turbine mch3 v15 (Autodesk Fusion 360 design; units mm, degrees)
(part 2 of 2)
sketch "Sketch44" plane through (0, -88, 0) normal (0, 1, 0) x axis (-1, 0, 0)
  line L1 (29.584, -10.378) -> (42.9468, -10.378)
  line L2 (29.584, 9.622) -> (29.584, -10.378)
  line L3 (48.5431, 9.622) -> (29.584, 9.622)
  line L4 (48.5431, -0.6848) -> (48.5431, 9.622)
  line L5 (59.9482, 19.0693) -> (48.5431, -0.6848)
  line L6 (63.7853, 19.9155) -> (59.9482, 19.0693)
  line L7 (46.4835, 42.382) -> (49.2565, 45.1551)
  line L8 (-46.4886, 42.382) -> (46.4835, 42.382)
  line L9 (-49.14, 45.2819) -> (-46.4886, 42.382)
  line L10 (-59.9456, 19.0649) -> (-63.7337, 20.0799)
  line L11 (-13.4596, -61.4513) -> (-59.9456, 19.0649)
  line L12 (-14.6453, -65.1974) -> (-13.4596, -61.4513)
  line L13 (13.4622, -61.4469) -> (14.4772, -65.235)
  line L14 (42.9468, -10.378) -> (13.4622, -61.4469)
  line L15 (16.2634, -23.1918) -> (16.634, -23.5625)
  line L16 (23.1436, -16.2151) -> (16.2634, -23.1918)
  line L17 (23.6506, -14.1336) -> (23.1436, -16.2151)
  line L18 (22.2443, -12.7273) -> (23.6506, -14.1336)
  line L19 (26.0227, -8.9488) -> (22.2443, -12.7273)
  line L20 (-16.2634, 23.1918) -> (-16.634, 23.5625)
  line L21 (-23.1436, 16.2151) -> (-16.2634, 23.1918)
  line L22 (-23.6506, 14.1336) -> (-23.1436, 16.2151)
  line L23 (-22.2443, 12.7273) -> (-23.6506, 14.1336)
  line L24 (-26.0227, 8.9488) -> (-22.2443, 12.7273)
  line L25 (-23.1918, -16.2634) -> (-23.5625, -16.634)
  line L26 (-16.2151, -23.1436) -> (-23.1918, -16.2634)
  line L27 (-14.1336, -23.6506) -> (-16.2151, -23.1436)
  line L28 (-12.7273, -22.2443) -> (-14.1336, -23.6506)
  line L29 (-8.9488, -26.0227) -> (-12.7273, -22.2443)
  line L30 (-36.2227, 9.0209) -> (-43.1621, 7.1615)
  line L31 (-38.7627, 4.6215) -> (-36.2227, 9.0209)
  line L32 (-43.1621, 7.1615) -> (-38.7627, 4.6215)
  line L33 (-52.8906, 15.7112) -> (-54.1606, 13.5115)
  line L34 (-51.9609, 12.2415) -> (-52.8906, 15.7112)
  line L35 (-54.1606, 13.5115) -> (-51.9609, 12.2415)
  line L36 (-42.0956, 34.4087) -> (-38.6259, 35.3384)
  line L37 (-37.6506, 42.1077) -> (-42.0956, 34.4087)
  line L38 (-33.2512, 39.5677) -> (-37.6506, 42.1077)
  line L39 (-36.7209, 38.638) -> (-33.2512, 39.5677)
  line L40 (-38.6259, 35.3384) -> (-36.7209, 38.638)
  line L41 (-24.7927, 28.8183) -> (-22.2527, 33.2177)
  line L42 (-26.6521, 35.7577) -> (-24.7927, 28.8183)
  line L43 (-22.2527, 33.2177) -> (-26.6521, 35.7577)
  line L44 (-18.5, 42.141) -> (-20.5, 42.141)
  line L45 (-18.5, 25) -> (-18.5, 42.141)
  line L46 (-20.5, 25) -> (-18.5, 25)
  line L47 (-20.5, 42.141) -> (-20.5, 25)
  line L48 (16, 26.3899) -> (16, 42.141)
  line L49 (23.1918, 16.2634) -> (23.5625, 16.634)
  line L50 (16.2151, 23.1436) -> (23.1918, 16.2634)
  line L51 (14.1336, 23.6506) -> (16.2151, 23.1436)
  line L52 (12.7273, 22.2443) -> (14.1336, 23.6506)
  line L53 (8.9488, 26.0227) -> (12.7273, 22.2443)
  line L54 (13.5, 42.141) -> (13.5, 26.8143)
  line L55 (16, 42.141) -> (13.5, 42.141)
  line L56 (-43.2694, 24.4155) -> (-22.8556, 24.4155)
  line L57 (-43.2694, 42.382) -> (-43.2694, 24.4155)
  line L58 (-22.8556, 42.382) -> (-43.2694, 42.382)
  line L59 (-22.8556, 24.4155) -> (-22.8556, 42.382)
  line L60 (-55.5462, 13.5115) -> (-38.7012, 1.0039)
  line L61 (-43.2694, 33.3988) -> (-55.5462, 13.5115)
  line L62 (-28.423, 24.4155) -> (-37.7467, 2.2894)
  arc A1 centre (0, 0) radius 66.8221 clockwise from (49.2565, 45.1551) to (63.7853, 19.9155)
  arc A2 centre (0, 0) radius 66.8221 clockwise from (-63.7337, 20.0799) to (-49.14, 45.2819)
  arc A3 centre (0, 0) radius 66.8221 clockwise from (14.4772, -65.235) to (-14.6453, -65.1974)
  arc A4 centre (16.2499, -12.9929) radius 10.5766 clockwise from (26.0227, -8.9488) to (16.634, -23.5625)
  arc A5 centre (-16.2499, 12.9929) radius 10.5766 clockwise from (-26.0227, 8.9488) to (-16.634, 23.5625)
  arc A6 centre (-12.9929, -16.2499) radius 10.5766 clockwise from (-8.9488, -26.0227) to (-23.5625, -16.634)
  arc A7 centre (12.9929, 16.2499) radius 10.5766 clockwise from (16, 26.3899) to (23.5625, 16.634)
  arc A8 centre (12.9929, 16.2499) radius 10.5766 clockwise from (8.9488, 26.0227) to (13.5, 26.8143)
  arc A9 centre (-38.224, 1.6467) radius 0.8006 clockwise from (-37.7467, 2.2894) to (-38.7012, 1.0039)
extrude "Extrude44" cut sketch "Sketch44" profile of L41 L43 L59 along normal blind 5
extrude "Extrude43" cut sketch "Sketch44" profile of L30 L31 L32 L33 L34 L35 L36 L37 L38 L39 L40 L41 L42 L43 L59 along normal blind 5
sketch "Sketch45" plane through (0, -88, 0) normal (0, 1, 0) x axis (-1, 0, 0)
  line L1 (29.584, -10.378) -> (42.9468, -10.378)
  line L2 (29.584, 9.622) -> (29.584, -10.378)
  line L3 (48.5431, 9.622) -> (29.584, 9.622)
  line L4 (48.5431, -0.6848) -> (48.5431, 9.622)
  line L5 (59.9482, 19.0693) -> (48.5431, -0.6848)
  line L6 (63.7853, 19.9155) -> (59.9482, 19.0693)
  line L7 (46.4835, 42.382) -> (49.2565, 45.1551)
  line L8 (-46.4886, 42.382) -> (46.4835, 42.382)
  line L9 (-49.14, 45.2819) -> (-46.4886, 42.382)
  line L10 (-59.9456, 19.0649) -> (-63.7337, 20.0799)
  line L11 (-13.4596, -61.4513) -> (-59.9456, 19.0649)
  line L12 (-14.6453, -65.1974) -> (-13.4596, -61.4513)
  line L13 (13.4622, -61.4469) -> (14.4772, -65.235)
  line L14 (42.9468, -10.378) -> (13.4622, -61.4469)
  line L15 (16.2634, -23.1918) -> (16.634, -23.5625)
  line L16 (23.1436, -16.2151) -> (16.2634, -23.1918)
  line L17 (23.6506, -14.1336) -> (23.1436, -16.2151)
  line L18 (22.2443, -12.7273) -> (23.6506, -14.1336)
  line L19 (26.0227, -8.9488) -> (22.2443, -12.7273)
  line L20 (-16.2634, 23.1918) -> (-16.634, 23.5625)
  line L21 (-23.1436, 16.2151) -> (-16.2634, 23.1918)
  line L22 (-23.6506, 14.1336) -> (-23.1436, 16.2151)
  line L23 (-22.2443, 12.7273) -> (-23.6506, 14.1336)
  line L24 (-26.0227, 8.9488) -> (-22.2443, 12.7273)
  line L25 (-23.1918, -16.2634) -> (-23.5625, -16.634)
  line L26 (-16.2151, -23.1436) -> (-23.1918, -16.2634)
  line L27 (-14.1336, -23.6506) -> (-16.2151, -23.1436)
  line L28 (-12.7273, -22.2443) -> (-14.1336, -23.6506)
  line L29 (-8.9488, -26.0227) -> (-12.7273, -22.2443)
  line L30 (-18.5, 42.141) -> (-20.5, 42.141)
  line L31 (-18.5, 25) -> (-18.5, 42.141)
  line L32 (-20.5, 25) -> (-18.5, 25)
  line L33 (-20.5, 42.141) -> (-20.5, 25)
  line L34 (16, 26.3899) -> (16, 42.141)
  line L35 (23.1918, 16.2634) -> (23.5625, 16.634)
  line L36 (16.2151, 23.1436) -> (23.1918, 16.2634)
  line L37 (14.1336, 23.6506) -> (16.2151, 23.1436)
  line L38 (12.7273, 22.2443) -> (14.1336, 23.6506)
  line L39 (8.9488, 26.0227) -> (12.7273, 22.2443)
  line L40 (13.5, 42.141) -> (13.5, 26.8143)
  line L41 (16, 42.141) -> (13.5, 42.141)
  line L42 (-55.7513, 18.9527) -> (-56.6274, 15.683)
  line L43 (-54.8883, 19.0667) -> (-55.8181, 15.597)
  line L44 (-57.6394, 22.1819) -> (-55.7513, 18.9527)
  line L45 (-56.4984, 26.4403) -> (-57.6394, 22.1819)
  line L46 (-49.2689, 30.6675) -> (-56.4984, 26.4403)
  line L47 (-41.82, 28.6716) -> (-49.2689, 30.6675)
  line L48 (-28.0102, 5.0536) -> (-41.82, 28.6716)
  line L49 (-30.2147, -3.1739) -> (-28.0102, 5.0536)
  line L50 (-41.0409, -9.5042) -> (-30.2147, -3.1739)
  line L51 (-43.9219, -8.689) -> (-41.0409, -9.5042)
  line L52 (-45.7338, -3.1852) -> (-46.183, -4.7727)
  line L53 (-56.6274, 15.683) -> (-45.7338, -3.1852)
  line L54 (-55.8181, 15.597) -> (-45.0231, -3.1005)
  line L55 (-30.8495, -2.2498) -> (-41.8481, -8.5998)
  line L56 (-47.9432, 0.6415) -> (-48.9675, 0.0501)
  line L57 (-58.5686, 18.7141) -> (-57.6394, 22.1819)
  line L58 (-56.6274, 15.3519) -> (-58.5686, 18.7141)
  line L59 (-56.6274, 15.683) -> (-56.6274, 15.3519)
  line L60 (-45, 32) -> (-43.1941, 29.0398)
  line L61 (-47.8204, 30.2794) -> (-45, 32)
  line L62 (-27.1598, -0.4207) -> (-28.7698, 2.2185)
  line L63 (-29.9298, -2.1105) -> (-27.1598, -0.4207)
  arc A1 centre (0, 0) radius 66.8221 clockwise from (49.2565, 45.1551) to (63.7853, 19.9155)
  arc A2 centre (0, 0) radius 66.8221 clockwise from (-63.7337, 20.0799) to (-49.14, 45.2819)
  arc A3 centre (0, 0) radius 66.8221 clockwise from (14.4772, -65.235) to (-14.6453, -65.1974)
  arc A4 centre (16.2499, -12.9929) radius 10.5766 clockwise from (26.0227, -8.9488) to (16.634, -23.5625)
  arc A5 centre (-16.2499, 12.9929) radius 10.5766 clockwise from (-26.0227, 8.9488) to (-16.634, 23.5625)
  arc A6 centre (-12.9929, -16.2499) radius 10.5766 clockwise from (-8.9488, -26.0227) to (-23.5625, -16.634)
  arc A7 centre (12.9929, 16.2499) radius 10.5766 clockwise from (16, 26.3899) to (23.5625, 16.634)
  arc A8 centre (12.9929, 16.2499) radius 10.5766 clockwise from (8.9488, 26.0227) to (13.5, 26.8143)
extrude "Extrude45" add sketch "Sketch45" profile of L11 L42 L44 L47 L49 L52 L53 L56 L57 L58 L59 L60 L61 L62 L63 along normal blind 3 taper -10
work_plane "WorkPlane13" AlongDistance 0
sketch "Sketch46" plane through (0, -100.3794, 0) normal (0, -1, 0) x axis (1, 0, 0)
  circle C1 centre (0, 0) radius 80
  dimension "d416" diameter C1 = 160
place_component sketch "Sketch46"
extrude "Extrude1" new body sketch "Sketch46" along normal blind 3
position "Position20"
sketch "Sketch47" plane through (0, -95.3483, 0) normal (0, 1, 0) x axis (-1, 0, 0)
  line L1 (-41.6932, 29.0398) -> (-43.4991, 32)
  line L2 (-46.3194, 30.2794) -> (-41.6932, 29.0398)
  line L3 (-43.4991, 32) -> (-46.3194, 30.2794)
  line L4 (-25.6588, -0.4207) -> (-27.2689, 2.2185)
  line L5 (-28.4289, -2.1105) -> (-25.6588, -0.4207)
  line L6 (-27.2689, 2.2185) -> (-28.4289, -2.1105)
  line L7 (-57.0677, 18.7141) -> (-55.1265, 15.3519)
  line L8 (-56.1385, 22.1819) -> (-57.0677, 18.7141)
  line L9 (-54.2504, 18.9527) -> (-56.1385, 22.1819)
  line L10 (-55.1265, 15.683) -> (-54.2504, 18.9527)
  line L11 (-55.1265, 15.3519) -> (-55.1265, 15.683)
  line L12 (17.5009, 26.3899) -> (17.5009, 42.141)
  line L13 (24.6928, 16.2634) -> (25.0634, 16.634)
  line L14 (17.7161, 23.1436) -> (24.6928, 16.2634)
  line L15 (15.6345, 23.6506) -> (17.7161, 23.1436)
  line L16 (14.2282, 22.2443) -> (15.6345, 23.6506)
  line L17 (10.4498, 26.0227) -> (14.2282, 22.2443)
  line L18 (15.0009, 42.141) -> (15.0009, 26.8143)
  line L19 (17.5009, 42.141) -> (15.0009, 42.141)
  line L20 (-16.9991, 42.141) -> (-18.9991, 42.141)
  line L21 (-16.9991, 25) -> (-16.9991, 42.141)
  line L22 (-18.9991, 25) -> (-16.9991, 25)
  line L23 (-18.9991, 42.141) -> (-18.9991, 25)
  line L24 (-21.6909, -16.2634) -> (-22.0615, -16.634)
  line L25 (-14.7142, -23.1436) -> (-21.6909, -16.2634)
  line L26 (-12.6327, -23.6506) -> (-14.7142, -23.1436)
  line L27 (-11.2263, -22.2443) -> (-12.6327, -23.6506)
  line L28 (-7.4479, -26.0227) -> (-11.2263, -22.2443)
  line L29 (-14.7625, 23.1918) -> (-15.1331, 23.5625)
  line L30 (-21.6426, 16.2151) -> (-14.7625, 23.1918)
  line L31 (-22.1497, 14.1336) -> (-21.6426, 16.2151)
  line L32 (-20.7434, 12.7273) -> (-22.1497, 14.1336)
  line L33 (-24.5218, 8.9488) -> (-20.7434, 12.7273)
  line L34 (17.7643, -23.1918) -> (18.135, -23.5625)
  line L35 (24.6445, -16.2151) -> (17.7643, -23.1918)
  line L36 (25.1516, -14.1336) -> (24.6445, -16.2151)
  line L37 (23.7452, -12.7273) -> (25.1516, -14.1336)
  line L38 (27.5237, -8.9488) -> (23.7452, -12.7273)
  line L39 (-46.4422, 0.6415) -> (-47.4665, 0.0501)
  line L40 (-44.2329, -3.1852) -> (-46.4422, 0.6415)
  line L41 (-44.6821, -4.7727) -> (-44.2329, -3.1852)
  line L42 (-11.9586, -61.4513) -> (-44.6821, -4.7727)
  line L43 (-13.1444, -65.1974) -> (-11.9586, -61.4513)
  line L44 (14.9631, -61.4469) -> (15.9781, -65.235)
  line L45 (44.4477, -10.378) -> (14.9631, -61.4469)
  line L46 (31.0849, -10.378) -> (44.4477, -10.378)
  line L47 (31.0849, 9.622) -> (31.0849, -10.378)
  line L48 (50.0441, 9.622) -> (31.0849, 9.622)
  line L49 (50.0441, -0.6848) -> (50.0441, 9.622)
  line L50 (61.4491, 19.0693) -> (50.0441, -0.6848)
  line L51 (65.2862, 19.9155) -> (61.4491, 19.0693)
  line L52 (47.9844, 42.382) -> (50.7575, 45.1551)
  line L53 (-44.9877, 42.382) -> (47.9844, 42.382)
  line L54 (-47.639, 45.2819) -> (-44.9877, 42.382)
  line L55 (-58.4447, 19.0649) -> (-62.2328, 20.0799)
  line L56 (-47.4665, 0.0501) -> (-58.4447, 19.0649)
  line L57 (-12.6055, -65.3161) -> (-11.9586, -61.4513)
  line L58 (-13.1444, -65.1974) -> (-11.9586, -61.4513)
  line L59 (-12.6055, -65.3161) -> (-13.1444, -65.1974)
  line L60 (65.2862, 19.9155) -> (61.4491, 19.0693)
  line L61 (65.2862, 19.9155) -> (61.4491, 19.0693)
  line L62 (65.1196, 20.4415) -> (65.2862, 19.9155)
  line L63 (65.1196, 20.4415) -> (61.4491, 19.0693)
  line L64 (-47.639, 45.2819) -> (-44.9877, 42.382)
  line L65 (-47.639, 45.2819) -> (-44.9877, 42.382)
  line L66 (-48.0113, 44.8746) -> (-47.639, 45.2819)
  line L67 (-48.0113, 44.8746) -> (-44.9877, 42.382)
  line L68 (-11.9586, -61.4513) -> (14.9631, -61.4469)
  line L69 (1.5036, -70) -> (1.5022, -61.4491)
  arc A1 centre (14.4938, 16.2499) radius 10.5766 clockwise from (17.5009, 26.3899) to (25.0634, 16.634)
  arc A2 centre (14.4938, 16.2499) radius 10.5766 clockwise from (10.4498, 26.0227) to (15.0009, 26.8143)
  arc A3 centre (-11.492, -16.2499) radius 10.5766 clockwise from (-7.4479, -26.0227) to (-22.0615, -16.634)
  arc A4 centre (-14.7489, 12.9929) radius 10.5766 clockwise from (-24.5218, 8.9488) to (-15.1331, 23.5625)
  arc A5 centre (17.7508, -12.9929) radius 10.5766 clockwise from (27.5237, -8.9488) to (18.135, -23.5625)
  arc A6 centre (1.5009, 0) radius 66.8221 clockwise from (15.9781, -65.235) to (-13.1444, -65.1974)
  arc A7 centre (1.5009, 0) radius 66.8221 clockwise from (50.7575, 45.1551) to (65.2862, 19.9155)
  arc A8 centre (1.5009, 0) radius 66.8221 clockwise from (-62.2328, 20.0799) to (-47.639, 45.2819)
  circle C1 centre (1.5036, -70) radius 1.6
  circle C2 centre (1.5036, -70) radius 5
extrude "Extrude46" cut sketch "Sketch47" profile of L43 L51 L54 L57 L58 L59 L60 L61 L62 L63 L64 L65 L66 L67 against normal blind 2
extrude "Extrude7" new body sketch "Sketch47" profile of A6 C1 C2 against normal blind 5
move "Move3" RotateAngle 1
copy_paste_bodies "CutPasteBodies2"
sketch "Sketch13" plane through (0, -14, 0) normal (0, -1, 0) x axis (1, 0, 0)
  line L1 (-1.9, 1.6248) -> (-1.9, -1.6248)
  arc A1 centre (0, 0) radius 2.5 clockwise from (-1.9, 1.6248) to (-1.9, -1.6248)
  circle C1 centre (0, 0) radius 9
  circle C2 centre (0, 0) radius 2.5
  circle C3 centre (0, 0) radius 2.5
revolve "Revolve4" sketch "Sketch8" AlongAngle 360
revolve "Revolve5" sketch "Sketch8" AlongAngle 360
work_plane "WorkPlane7" AlongDistance -9
sketch "Sketch14"
  line L1 (138.1715, -105.0631) -> (15.2987, -19.0267)
  line L2 (-5.4, -27) -> (-5.4, -23.2)
  line L3 (32.4214, -32.9767) -> (35.2214, -32.9767)
  line L4 (12.5, -15) -> (18.5775, -19.2555)
  line L5 (9.9406, -15) -> (12.5, -15)
  line L6 (11.2203, -15) -> (35.2214, -32.9767)
  line L7 (12.5, -15) -> (11.2203, -15)
  line L8 (18.5775, -19.2555) -> (12.5, -15)
  arc A1 centre (-20.3702, -142.7413) radius 121.7999 clockwise from (24.1757, -29.3795) to (49.4914, -42.9686)
  arc A2 centre (-60.2315, -131.8065) radius 137.3994 clockwise from (18.5775, -19.2555) to (35.2214, -32.9767)
  point P9 (35.2214, -32.9767)
  point P10 (32.4214, -32.9767)
  dimension "d109" distance P9 P10 = 2.8
revolve "Revolve3" sketch "Sketch14" AlongAngle 360
extrude "Extrude1" cut sketch "Sketch12" profile of L1 C10 against normal blind 16.3
extrude "Extrude2" cut sketch "Sketch1" profile of C1 along normal blind 40
revolve "Revolve3" sketch "Sketch8" AlongAngle -30
circular_pattern "C-Pattern2" TotalAngle 360
combine "Combine2"
revolve "Revolve5" sketch "Sketch8" AlongAngle 360
revolve "Revolve6" sketch "Sketch8" AlongAngle 30
revolve "Revolve7" sketch "Sketch8" AlongAngle -30
extrude "Extrude2" add of existing geometry blind 10
combine "Combine2"
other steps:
base_feature "Base Feature1" bodies "Race outer"
extrude "Extrude1" new body sketch "Sketch1" blind 0.1 named "d18_5" bodies "LED1206FAB"
extrude "Extrude1" new body sketch "Sketch1" blind 0.1 named "d20_2" bodies "R1206FAB"
extrude "Extrude1" new body sketch "Sketch1" blind 0.1 named "d6_2" bodies "C1206FAB"
extrude "Extrude1" new body sketch "Sketch1" blind 0.1 bodies "SOIC14"
extrude "Extrude1" new body sketch "Sketch1" blind 0.1 named "d10_2" bodies "SOT23"
extrude "Extrude1" new body sketch "Sketch1" blind 0.1 bodies "2X03SMD"
extrude "Extrude1" new body sketch "Sketch1" blind 0.1 bodies "2X02SMD"
extrude "Extrude1" new body sketch "Sketch1" blind 0.1 named "d16_2" bodies "R1206FAB"
extrude "Extrude1" new body sketch "Sketch1" blind 0.1 named "d18_2" bodies "P-LCC-4"
extrude "Extrude1" new body sketch "Sketch1" blind 0.1 named "d4_2" bodies "C1206FAB"
extrude "Extrude1" new body sketch "Sketch1" blind 0.1 named "d6_7" bodies "SOIC8"
extrude "Extrude1" new body sketch "Sketch1" blind 0.1 named "d8_6" bodies "R1206FAB"
extrude "Extrude1" new body sketch "Sketch1" blind 0.1 named "d10_7" bodies "2X03SMD"
extrude "Extrude1" new body sketch "Sketch1" blind 0.1 named "d12_7" bodies "OP1206"
extrude "Extrude1" new body sketch "Sketch1" blind 0.1 named "d14_5" bodies "2X02SMD"
extrude "Extrude1" new body sketch "Sketch1" blind 0.1 named "d16_6" bodies "SOT23"
extrude "Extrude1" new body sketch "Sketch1" blind 1.57 named "d2_2" bodies "Board"
extrude "Extrude1" new body sketch "Sketch1" blind 0.1 named "d6_6" bodies "PJ-002AH-SMT"
extrude "Extrude1" new body sketch "Sketch1" blind 0.1 named "d8_5" bodies "R1206FAB"
extrude "Extrude1" new body sketch "Sketch1" blind 0.1 named "d10_6" bodies "2X02SMD"
extrude "Extrude1" new body sketch "Sketch1" blind 0.1 named "d12_6" bodies "LED1206FAB"
extrude "Extrude1" new body sketch "Sketch1" blind 2.542 named "d32_2" bodies "TQFP32-08"
extrude "Extrude1" new body sketch "Sketch1" blind 1.57 named "d2_7" bodies "Board"
extrude "Extrude2" sketch "Sketch2" blind 1.57 named "d4_1"
extrude "Extrude1" new body sketch "Sketch1" blind 0.1 named "d6_3" bodies "C1206FAB"
extrude "Extrude1" new body sketch "Sketch1" blind 0.1 named "d8_2" bodies "SOIC14"
extrude "Extrude1" new body sketch "Sketch1" blind 0.1 named "d10_3" bodies "SOT23"
extrude "Extrude1" new body sketch "Sketch1" blind 0.1 named "d12_3" bodies "2X03SMD"
extrude "Extrude1" new body sketch "Sketch1" blind 0.1 named "d14_2" bodies "2X02SMD"
extrude "Extrude1" new body sketch "Sketch1" blind 0.1 named "d16_3" bodies "R1206FAB"
extrude "Extrude1" new body sketch "Sketch1" blind 0.1 named "d18_3" bodies "P-LCC-4"
extrude "Extrude1" new body sketch "Sketch1" blind 0.1 named "d6_4" bodies "C1206FAB"
extrude "Extrude1" new body sketch "Sketch1" blind 0.1 named "d8_3" bodies "R1206FAB"
extrude "Extrude1" new body sketch "Sketch1" blind 0.1 named "d10_4" bodies "2X03SMD"
extrude "Extrude1" new body sketch "Sketch1" blind 0.1 named "d12_4" bodies "1X06SMD"
extrude "Extrude1" new body sketch "Sketch1" blind 0.1 named "d14_3" bodies "EFOBM"
extrude "Extrude1" new body sketch "Sketch1" blind 0.1 named "d16_4" bodies "LED1206FAB"
extrude "Extrude1" new body sketch "Sketch1" blind 0.1 bodies "ELLCTV"
extrude "Extrude1" new body sketch "Sketch1" blind 0.1 named "d22_3" bodies "SOD123"
extrude "Extrude1" new body sketch "Sketch1" blind 0.1 named "d24_2" bodies "TO252"
extrude "Extrude1" new body sketch "Sketch1" blind 0.1 named "d26_1" bodies "BFC"
extrude "Extrude1" new body sketch "Sketch1" blind 0.1 named "d28_1" bodies "2X02SMD"
extrude "Extrude1" new body sketch "Sketch1" blind 0.1 named "d6_5" bodies "C1206FAB"
extrude "Extrude1" new body sketch "Sketch1" blind 0.1 named "d8_4" bodies "SOIC14"
extrude "Extrude1" new body sketch "Sketch1" blind 0.1 named "d10_5" bodies "SOT23"
extrude "Extrude1" new body sketch "Sketch1" blind 0.1 named "d12_5" bodies "2X03SMD"
extrude "Extrude1" new body sketch "Sketch1" blind 0.1 named "d14_4" bodies "2X02SMD"
extrude "Extrude1" new body sketch "Sketch1" blind 0.1 named "d16_5" bodies "R1206FAB"
extrude "Extrude1" new body sketch "Sketch1" blind 0.1 named "d18_4" bodies "P-LCC-4"
extrude "Extrude1" new body sketch "Sketch1" blind 1.57 named "d2_6" bodies "Board"
extrude "Extrude2" sketch "Sketch2" blind 1.57 named "d4_3"
extrude "Extrude1" new body sketch "Sketch1" blind 1.57 named "d2_3" bodies "Board"
extrude "Extrude1" new body sketch "Sketch1" blind 1.57 named "d2_4" bodies "Board"
extrude "Extrude4" sketch "Sketch4" blind 1.57 named "d22_1"
extrude "Extrude3" sketch "Sketch3" blind 1.57 named "d30_1"
extrude "Extrude1" new body sketch "Sketch1" blind 1.57 named "d2_5" bodies "Board"
extrude "Extrude4" sketch "Sketch4" blind 1.57 named "d22_2"
revolve "Revolve1" sketch "Sketch2" AlongAngle 180
revolve "Revolve2" sketch "Sketch2" AlongAngle -180
move "Move1"
base_feature "Base Feature1"
base_feature "Base Feature2"
base_feature "Base Feature1" bodies "bottom"
fillet "Fillet1" radius 0.4
fillet "Fillet2" radius 0.4
base_feature "Base Feature1" bodies "Race inner bottom"
base_feature "Base Feature3" bodies "race inner (1)"
create_component "CreateComponent3"
create_component "CreateComponent4"
create_component "CreateComponent1"
create_component "CreateComponent3"
create_component "CreateComponent4"
create_component "CreateComponent5"
create_component "CreateComponent6"
remove_body "RemoveBody1"
create_component "CreateComponent5"
remove_body "RemoveBody1"
remove_body "RemoveBody2"
remove_body "RemoveBody3"
remove_body "RemoveBody4"
remove_body "RemoveBody5"
remove_body "RemoveBody6"
remove_body "RemoveBody1"
extrude "Extrude5" cut sketch "Sketch12" profile of L1 C10 against normal blind 16.3
base_feature "Base Feature2" bodies "race inner"
remove_body "RemoveBody7"
remove_body "RemoveBody8"
create_component "CreateComponent7"
remove_body "RemoveBody1"
create_component "CreateComponent1"
remove_body "RemoveBody1"
create_component "CreateComponent1"
create_component "CreateComponent1"
sketch "Sketch1"
  line L1 (51.967, -44.579) -> (-52.641, -44.634)
  line L2 (52.118, -9.984) -> (51.967, -44.579)
  line L3 (-52.744, -10.167) -> (52.118, -9.984)
  line L4 (-52.641, -44.634) -> (-52.744, -10.167)
canvas "Canvas1"
canvas "Canvas2"
sketch "Sketch2"
  circle C1 centre (-11.303, -19.558) radius 0.175
  circle C2 centre (-2.54, -17.907) radius 0.175
  circle C3 centre (44.704, -14.478) radius 0.175
  circle C4 centre (39.243, -25.908) radius 0.175
  circle C5 centre (36.068, -28.194) radius 0.175
  circle C6 centre (28.956, -32.385) radius 0.175
  circle C7 centre (22.225, -34.925) radius 0.175
  circle C8 centre (15.24, -36.957) radius 0.175
  circle C9 centre (7.239, -38.608) radius 0.175
  circle C10 centre (-9.525, -35.179) radius 0.175
  circle C11 centre (48.514, -18.161) radius 0.175
  circle C12 centre (42.672, -23.368) radius 0.175
  circle C13 centre (41.275, -21.59) radius 0.175
  circle C14 centre (34.163, -24.765) radius 0.175
  circle C15 centre (18.796, -29.21) radius 0.175
  circle C16 centre (-5.461, -32.766) radius 0.175
  circle C17 centre (-17.907, -32.766) radius 0.175
  circle C18 centre (42.672, -18.161) radius 0.175
  circle C19 centre (36.83, -22.987) radius 0.175
  circle C20 centre (27.273, -28.035) radius 0.175
  circle C21 centre (-38.1, -28.575) radius 0.175
  circle C22 centre (-44.584, -23.756) radius 0.175
  circle C23 centre (-25.908, -31.369) radius 0.175
  circle C24 centre (21.336, -31.369) radius 0.175
  circle C25 centre (-5.461, -39.243) radius 0.175
  circle C26 centre (14.478, -33.401) radius 0.175
  circle C27 centre (1.905, -38.989) radius 0.175
  circle C28 centre (-34.544, -30.861) radius 0.175
  circle C29 centre (-42.862, -21.272) radius 0.175
  circle C30 centre (-26.924, -33.655) radius 0.175
  circle C31 centre (4.956, -33.524) radius 0.175
  circle C32 centre (-5.461, -34.925) radius 0.175
  circle C33 centre (-44.704, -16.383) radius 0.175
  circle C34 centre (-11.43, -17.272) radius 0.175
  circle C35 centre (-15.494, -17.272) radius 0.175
create_component "CreateComponent2" sketch "Sketch1"
sketch "Sketch1"
  line L1 (2.032, -1.016) -> (-2.032, -1.016)
  line L2 (2.032, 1.016) -> (2.032, -1.016)
  line L3 (-2.032, 1.016) -> (2.032, 1.016)
  line L4 (-2.032, -1.016) -> (-2.032, 1.016)
create_component "CreateComponent3" sketch "Sketch1"
sketch "Sketch1"
  line L1 (4.267, -2.858) -> (-4.267, -2.858)
  line L2 (4.267, 2.858) -> (4.267, -2.858)
  line L3 (-4.267, 2.858) -> (4.267, 2.858)
  line L4 (-4.267, -2.858) -> (-4.267, 2.858)
create_component "CreateComponent4" sketch "Sketch1"
sketch "Sketch1"
  line L1 (1.422, -1.295) -> (-1.422, -1.295)
  line L2 (1.422, 1.295) -> (1.422, -1.295)
  line L3 (-1.422, 1.295) -> (1.422, 1.295)
  line L4 (-1.422, -1.295) -> (-1.422, 1.295)
create_component "CreateComponent5" sketch "Sketch1"
sketch "Sketch1"
  line L1 (4.19, -3.175) -> (-3.81, -3.175)
  line L2 (4.19, 3.175) -> (4.19, -3.175)
  line L3 (-3.81, 3.175) -> (4.19, 3.175)
  line L4 (-3.81, -3.175) -> (-3.81, 3.175)
create_component "CreateComponent6" sketch "Sketch1"
sketch "Sketch1"
  line L1 (4.19, -1.905) -> (-3.81, -1.905)
  line L2 (4.19, 1.905) -> (4.19, -1.905)
  line L3 (-3.81, 1.905) -> (4.19, 1.905)
  line L4 (-3.81, -1.905) -> (-3.81, 1.905)
create_component "CreateComponent7" sketch "Sketch1"
sketch "Sketch1"
  line L1 (2.032, -1.016) -> (-2.032, -1.016)
  line L2 (2.032, 1.016) -> (2.032, -1.016)
  line L3 (-2.032, 1.016) -> (2.032, 1.016)
  line L4 (-2.032, -1.016) -> (-2.032, 1.016)
create_component "CreateComponent8" sketch "Sketch1"
sketch "Sketch1"
  line L1 (1.4, -1.8) -> (-2.032, -1.8)
  line L2 (1.4, 1.8) -> (1.4, -1.8)
  line L3 (-2.032, 1.8) -> (1.4, 1.8)
  line L4 (-2.032, -1.8) -> (-2.032, 1.8)
as_built_joint "As-built1"
create_component "CreateComponent9"
create_component "CreateComponent1"
create_component "CreateComponent1"
sketch "Sketch1"
  line L1 (101.092, 29.718) -> (8.89, 29.718)
  line L2 (109.22, 20.828) -> (101.092, 29.718)
  line L3 (8.89, 29.718) -> (0, 20.828)
  arc A1 centre (54.61, 75.438) radius 77.2302 clockwise from (109.22, 20.828) to (0, 20.828)
  circle C1 centre (24.892, 24.511) radius 1.437
  circle C2 centre (79.502, 24.257) radius 1.374
create_component "CreateComponent2" sketch "Sketch1"
sketch "Sketch1"
  line L1 (2.032, -1.016) -> (-2.032, -1.016)
  line L2 (2.032, 1.016) -> (2.032, -1.016)
  line L3 (-2.032, 1.016) -> (2.032, 1.016)
  line L4 (-2.032, -1.016) -> (-2.032, 1.016)
create_component "CreateComponent3" sketch "Sketch1"
sketch "Sketch1"
  line L1 (4.267, -2.858) -> (-4.267, -2.858)
  line L2 (4.267, 2.858) -> (4.267, -2.858)
  line L3 (-4.267, 2.858) -> (4.267, 2.858)
  line L4 (-4.267, -2.858) -> (-4.267, 2.858)
create_component "CreateComponent4" sketch "Sketch1"
sketch "Sketch1"
  line L1 (1.422, -1.295) -> (-1.422, -1.295)
  line L2 (1.422, 1.295) -> (1.422, -1.295)
  line L3 (-1.422, 1.295) -> (1.422, 1.295)
  line L4 (-1.422, -1.295) -> (-1.422, 1.295)
create_component "CreateComponent5" sketch "Sketch1"
sketch "Sketch1"
  line L1 (4.19, -3.175) -> (-3.81, -3.175)
  line L2 (4.19, 3.175) -> (4.19, -3.175)
  line L3 (-3.81, 3.175) -> (4.19, 3.175)
  line L4 (-3.81, -3.175) -> (-3.81, 3.175)
create_component "CreateComponent6" sketch "Sketch1"
sketch "Sketch1"
  line L1 (4.19, -1.905) -> (-3.81, -1.905)
  line L2 (4.19, 1.905) -> (4.19, -1.905)
  line L3 (-3.81, 1.905) -> (4.19, 1.905)
  line L4 (-3.81, -1.905) -> (-3.81, 1.905)
create_component "CreateComponent7" sketch "Sketch1"
sketch "Sketch1"
  line L1 (2.032, -1.016) -> (-2.032, -1.016)
  line L2 (2.032, 1.016) -> (2.032, -1.016)
  line L3 (-2.032, 1.016) -> (2.032, 1.016)
  line L4 (-2.032, -1.016) -> (-2.032, 1.016)
create_component "CreateComponent8" sketch "Sketch1"
sketch "Sketch1"
  line L1 (1.4, -1.8) -> (-2.032, -1.8)
  line L2 (1.4, 1.8) -> (1.4, -1.8)
  line L3 (-2.032, 1.8) -> (1.4, 1.8)
  line L4 (-2.032, -1.8) -> (-2.032, 1.8)
canvas "Canvas5"
canvas "Canvas6"
sketch "Sketch4"
  circle C1 centre (42.037, 22.098) radius 0.47
  circle C2 centre (47.879, 23.495) radius 0.47
  circle C3 centre (95.631, 13.97) radius 0.47
  circle C4 centre (99.695, 23.749) radius 0.47
  circle C5 centre (46.355, 2.921) radius 0.47
  circle C6 centre (60.833, 1.397) radius 0.47
  circle C7 centre (77.724, 4.826) radius 0.47
  circle C8 centre (69.977, 3.302) radius 0.47
  circle C9 centre (85.217, 7.874) radius 0.47
  circle C10 centre (92.964, 11.811) radius 0.47
  circle C11 centre (98.679, 18.122) radius 0.47
  circle C12 centre (37.129, 5.461) radius 0.47
  circle C13 centre (56.388, 4.318) radius 0.47
  circle C14 centre (72.136, 7.366) radius 0.47
  circle C15 centre (29.845, 9.398) radius 0.47
  circle C16 centre (16.383, 10.963) radius 0.47
  circle C17 centre (57.912, 6.985) radius 0.47
  circle C18 centre (38.989, 5.588) radius 0.47
  circle C19 centre (48.553, 2.706) radius 0.47
  circle C20 centre (76.073, 8.382) radius 0.47
  circle C21 centre (10.522, 18.65) radius 0.47
  circle C22 centre (20.955, 10.414) radius 0.47
  circle C23 centre (53.975, 2.921) radius 0.47
  circle C24 centre (68.707, 6.731) radius 0.47
  circle C25 centre (8.509, 24.638) radius 0.47
  circle C26 centre (36.322, 24.257) radius 0.47
  circle C27 centre (40.386, 24.384) radius 0.47
as_built_joint "As-built3"
create_component "CreateComponent11"
create_component "CreateComponent16"
create_component "CreateComponent17"
create_component "CreateComponent1"
create_component "CreateComponent1"
sketch "Sketch1"
  line L1 (101.346, 32.258) -> (9.906, 32.258)
  line L2 (9.906, 32.258) -> (1.016, 23.368)
  line L3 (110.236, 23.368) -> (101.346, 32.258)
  arc A1 centre (55.626, 77.978) radius 77.2302 clockwise from (110.236, 23.368) to (1.016, 23.368)
  circle C1 centre (26.416, 27.686) radius 1.778
  circle C2 centre (80.518, 27.686) radius 1.778
create_component "CreateComponent2" sketch "Sketch1"
sketch "Sketch1"
  line L1 (2.032, -1.016) -> (-2.032, -1.016)
  line L2 (2.032, 1.016) -> (2.032, -1.016)
  line L3 (-2.032, 1.016) -> (2.032, 1.016)
  line L4 (-2.032, -1.016) -> (-2.032, 1.016)
create_component "CreateComponent3" sketch "Sketch1"
sketch "Sketch1"
  line L1 (4.267, -2.858) -> (-4.267, -2.858)
  line L2 (4.267, 2.858) -> (4.267, -2.858)
  line L3 (-4.267, 2.858) -> (4.267, 2.858)
  line L4 (-4.267, -2.858) -> (-4.267, 2.858)
create_component "CreateComponent4" sketch "Sketch1"
sketch "Sketch1"
  line L1 (1.422, -1.295) -> (-1.422, -1.295)
  line L2 (1.422, 1.295) -> (1.422, -1.295)
  line L3 (-1.422, 1.295) -> (1.422, 1.295)
  line L4 (-1.422, -1.295) -> (-1.422, 1.295)
create_component "CreateComponent5" sketch "Sketch1"
sketch "Sketch1"
  line L1 (4.19, -3.175) -> (-3.81, -3.175)
  line L2 (4.19, 3.175) -> (4.19, -3.175)
  line L3 (-3.81, 3.175) -> (4.19, 3.175)
  line L4 (-3.81, -3.175) -> (-3.81, 3.175)
create_component "CreateComponent6" sketch "Sketch1"
sketch "Sketch1"
  line L1 (4.19, -1.905) -> (-3.81, -1.905)
  line L2 (4.19, 1.905) -> (4.19, -1.905)
  line L3 (-3.81, 1.905) -> (4.19, 1.905)
  line L4 (-3.81, -1.905) -> (-3.81, 1.905)
create_component "CreateComponent7" sketch "Sketch1"
sketch "Sketch1"
  line L1 (2.032, -1.016) -> (-2.032, -1.016)
  line L2 (2.032, 1.016) -> (2.032, -1.016)
  line L3 (-2.032, 1.016) -> (2.032, 1.016)
  line L4 (-2.032, -1.016) -> (-2.032, 1.016)
create_component "CreateComponent8" sketch "Sketch1"
sketch "Sketch1"
  line L1 (1.4, -1.8) -> (-2.032, -1.8)
  line L2 (1.4, 1.8) -> (1.4, -1.8)
  line L3 (-2.032, 1.8) -> (1.4, 1.8)
  line L4 (-2.032, -1.8) -> (-2.032, 1.8)
canvas "Canvas5"
canvas "Canvas6"
sketch "Sketch4"
  circle C1 centre (43.053, 24.638) radius 0.47
  circle C2 centre (48.895, 26.035) radius 0.47
  circle C3 centre (100.711, 26.289) radius 0.47
  circle C4 centre (97.425, 16.113) radius 0.4955
  circle C5 centre (47.371, 5.461) radius 0.47
  circle C6 centre (61.849, 3.937) radius 0.47
  circle C7 centre (78.74, 7.366) radius 0.47
  circle C8 centre (70.993, 5.842) radius 0.47
  circle C9 centre (86.233, 10.414) radius 0.47
  circle C10 centre (99.695, 20.662) radius 0.47
  circle C11 centre (93.87, 14.461) radius 0.4955
  circle C12 centre (38.145, 8.001) radius 0.47
  circle C13 centre (57.404, 6.858) radius 0.47
  circle C14 centre (73.152, 9.906) radius 0.47
  circle C15 centre (58.928, 9.525) radius 0.47
  circle C16 centre (30.988, 10.922) radius 0.4955
  circle C17 centre (16.691, 13.817) radius 0.4955
  circle C18 centre (40.005, 8.128) radius 0.47
  circle C19 centre (49.569, 5.246) radius 0.47
  circle C20 centre (77.089, 10.922) radius 0.47
  circle C21 centre (7.112, 21.844) radius 0.4955
  circle C22 centre (14.478, 16.764) radius 0.4955
  circle C23 centre (22.705, 14.069) radius 0.4955
  circle C24 centre (54.991, 5.461) radius 0.47
  circle C25 centre (69.723, 9.271) radius 0.47
  circle C26 centre (29.112, 7.781) radius 0.4955
  circle C27 centre (9.144, 24.384) radius 0.4955
  circle C28 centre (37.338, 26.797) radius 0.47
  circle C29 centre (41.402, 26.924) radius 0.47
  circle C30 centre (56.388, 22.86) radius 0.47
  circle C31 centre (52.07, 25.4) radius 0.47
  circle C32 centre (54.356, 25.763) radius 0.47
  circle C33 centre (55.878, 20.064) radius 0.47
as_built_joint "As-built3"
create_component "CreateComponent19"
create_component "CreateComponent20"
create_component "CreateComponent1"
create_component "CreateComponent1"
sketch "Sketch1"
  line L1 (0, 0) -> (0, 31.42)
  line L2 (0, 31.75) -> (0, 0)
  line L3 (21.59, 31.75) -> (0, 31.75)
  line L4 (21.59, 6.35) -> (21.59, 31.75)
  line L5 (15.24, 0) -> (21.59, 6.35)
  line L6 (0, 0) -> (15.24, 0)
  line L7 (0, 31.42) -> (0, 0)
  circle C1 centre (16.51, 27.94) radius 1.796
canvas "Canvas1"
canvas "Canvas2"
sketch "Sketch2"
  circle C1 centre (10.16, 6.49) radius 0.8
  circle C2 centre (10.16, 10.99) radius 0.9
create_component "CreateComponent2" sketch "Sketch1"
sketch "Sketch1"
  line L1 (7.4, -6.4) -> (-7.4, -6.4)
  line L2 (7.4, 6.4) -> (7.4, -6.4)
  line L3 (-7.4, 6.4) -> (7.4, 6.4)
  line L4 (-7.4, -6.4) -> (-7.4, 6.4)
create_component "CreateComponent3" sketch "Sketch1"
sketch "Sketch1"
  line L1 (2.032, -1.016) -> (-2.032, -1.016)
  line L2 (2.032, 1.016) -> (2.032, -1.016)
  line L3 (-2.032, 1.016) -> (2.032, 1.016)
  line L4 (-2.032, -1.016) -> (-2.032, 1.016)
create_component "CreateComponent4" sketch "Sketch1"
sketch "Sketch1"
  line L1 (4.19, -1.905) -> (-3.81, -1.905)
  line L2 (4.19, 1.905) -> (4.19, -1.905)
  line L3 (-3.81, 1.905) -> (4.19, 1.905)
  line L4 (-3.81, -1.905) -> (-3.81, 1.905)
create_component "CreateComponent5" sketch "Sketch1"
sketch "Sketch1"
  line L1 (2.032, -1.016) -> (-2.032, -1.016)
  line L2 (2.032, 1.016) -> (2.032, -1.016)
  line L3 (-2.032, 1.016) -> (2.032, 1.016)
  line L4 (-2.032, -1.016) -> (-2.032, 1.016)
as_built_joint "As-built1"
create_component "CreateComponent21"
create_component "CreateComponent23"
remove_body "RemoveBody1"
create_component "CreateComponent24" sketch "Sketch29"
create_component "CreateComponent27"
create_component "CreateComponent28"
remove_body "RemoveBody9"
remove_body "RemoveBody1"
create_component "CreateComponent1"
create_component "CreateComponent1"
sketch "Sketch1"
  line L1 (-2.159, 71.755) -> (-2.159, 45.085)
  line L2 (1.905, 41.148) -> (37.465, 41.148)
  line L3 (-2.032, 45.085) -> (1.905, 41.148)
  line L4 (-2.159, 45.085) -> (-2.032, 45.085)
  line L5 (1.016, 74.93) -> (-2.159, 71.755)
  line L6 (13.081, 74.93) -> (1.016, 74.93)
  line L7 (14.351, 73.66) -> (13.081, 74.93)
  line L8 (29.591, 73.66) -> (14.351, 73.66)
  line L9 (30.734, 74.803) -> (29.591, 73.66)
  line L10 (40.767, 74.803) -> (30.734, 74.803)
  line L11 (41.148, 74.422) -> (40.767, 74.803)
  line L12 (51.435, 74.422) -> (41.148, 74.422)
  line L13 (54.61, 71.247) -> (51.435, 74.422)
  line L14 (54.61, 65.151) -> (54.61, 71.247)
  line L15 (55.753, 64.008) -> (54.61, 65.151)
  line L16 (55.753, 51.308) -> (55.753, 64.008)
  line L17 (52.07, 47.625) -> (55.753, 51.308)
  line L18 (40.386, 47.625) -> (52.07, 47.625)
  line L19 (40.259, 47.752) -> (40.386, 47.625)
  line L20 (39.116, 46.609) -> (40.259, 47.752)
  line L21 (39.116, 42.799) -> (39.116, 46.609)
  line L22 (37.465, 41.148) -> (39.116, 42.799)
create_component "CreateComponent2" sketch "Sketch1"
sketch "Sketch1"
  line L1 (2.032, -1.016) -> (-2.032, -1.016)
  line L2 (2.032, 1.016) -> (2.032, -1.016)
  line L3 (-2.032, 1.016) -> (2.032, 1.016)
  line L4 (-2.032, -1.016) -> (-2.032, 1.016)
create_component "CreateComponent3" sketch "Sketch1"
sketch "Sketch1"
  line L1 (2.032, -1.016) -> (-2.032, -1.016)
  line L2 (2.032, 1.016) -> (2.032, -1.016)
  line L3 (-2.032, 1.016) -> (2.032, 1.016)
  line L4 (-2.032, -1.016) -> (-2.032, 1.016)
create_component "CreateComponent4" sketch "Sketch1"
sketch "Sketch1"
  line L1 (4.19, -3.175) -> (-3.81, -3.175)
  line L2 (4.19, 3.175) -> (4.19, -3.175)
  line L3 (-3.81, 3.175) -> (4.19, 3.175)
  line L4 (-3.81, -3.175) -> (-3.81, 3.175)
create_component "CreateComponent5" sketch "Sketch1"
sketch "Sketch1"
  line L1 (1.27, -6.985) -> (-1.27, -6.985)
  line L2 (1.27, 6.985) -> (1.27, -6.985)
  line L3 (-1.27, 6.985) -> (1.27, 6.985)
  line L4 (-1.27, -6.985) -> (-1.27, 6.985)
create_component "CreateComponent6" sketch "Sketch1"
sketch "Sketch1"
  line L1 (1.75, -1.95) -> (-1.75, -1.95)
  line L2 (1.75, 1.95) -> (1.75, -1.95)
  line L3 (-1.75, 1.95) -> (1.75, 1.95)
  line L4 (-1.75, -1.95) -> (-1.75, 1.95)
create_component "CreateComponent7" sketch "Sketch1"
sketch "Sketch1"
  line L1 (2.032, -1.016) -> (-2.032, -1.016)
  line L2 (2.032, 1.016) -> (2.032, -1.016)
  line L3 (-2.032, 1.016) -> (2.032, 1.016)
  line L4 (-2.032, -1.016) -> (-2.032, 1.016)
create_component "CreateComponent9" sketch "Sketch1"
sketch "Sketch1"
  line L1 (6, -6) -> (-6, -6)
  line L2 (6, 6) -> (6, -6)
  line L3 (-6, 6) -> (6, 6)
  line L4 (-6, -6) -> (-6, 6)
create_component "CreateComponent10" sketch "Sketch1"
sketch "Sketch1"
  line L1 (2.794, -0.889) -> (-2.921, -0.889)
  line L2 (2.794, 0.889) -> (2.794, -0.889)
  line L3 (-2.921, 0.889) -> (2.794, 0.889)
  line L4 (-2.921, -0.889) -> (-2.921, 0.889)
create_component "CreateComponent11" sketch "Sketch1"
sketch "Sketch1"
  line L1 (3.277, -5.156) -> (-3.277, -5.156)
  line L2 (3.277, 5.105) -> (3.277, -5.156)
  line L3 (-3.277, 5.105) -> (3.277, 5.105)
  line L4 (-3.277, -5.156) -> (-3.277, 5.105)
create_component "CreateComponent12" sketch "Sketch1"
sketch "Sketch1"
  line L1 (9.982, -9.982) -> (-9.982, -9.982)
  line L2 (9.982, 9.982) -> (9.982, -9.982)
  line L3 (-9.982, 9.982) -> (9.982, 9.982)
  line L4 (-9.982, -9.982) -> (-9.982, 9.982)
create_component "CreateComponent13" sketch "Sketch1"
sketch "Sketch1"
  line L1 (4.19, -1.905) -> (-3.81, -1.905)
  line L2 (4.19, 1.905) -> (4.19, -1.905)
  line L3 (-3.81, 1.905) -> (4.19, 1.905)
  line L4 (-3.81, -1.905) -> (-3.81, 1.905)
canvas "Canvas3"
canvas "Canvas4"
sketch "Sketch3"
  circle C1 centre (14.732, 55.982) radius 1.016
  circle C2 centre (14.732, 65.938) radius 1.016
  circle C3 centre (51.435, 51.41) radius 1.016
  circle C4 centre (51.435, 61.366) radius 1.016
create_component "CreateComponent14" sketch "Sketch1"
sketch "Sketch1"
  line L1 (4.9276, 4.9276) -> (-4.9276, 4.9276)
  line L2 (4.9276, -4.9276) -> (4.9276, 4.9276)
  line L3 (-4.9276, -4.9276) -> (4.9276, -4.9276)
  line L4 (-4.9276, 4.9276) -> (-4.9276, -4.9276)
as_built_joint "As-built2"
create_component "CreateComponent29"
create_component "CreateComponent30"
create_component "CreateComponent1"
create_component "CreateComponent1"
sketch "Sketch1"
  line L1 (5.08, 19.05) -> (0, 13.97)
  line L2 (31.75, 19.05) -> (5.08, 19.05)
  line L3 (36.83, 13.97) -> (31.75, 19.05)
  line L4 (36.83, 1.27) -> (36.83, 13.97)
  line L5 (8.89, 1.27) -> (30.48, 1.27)
  line L6 (6.35, 3.81) -> (8.89, 1.27)
  line L7 (2.54, 3.81) -> (6.35, 3.81)
  line L8 (0, 6.35) -> (2.54, 3.81)
  line L9 (0, 13.97) -> (0, 6.35)
  line L10 (31.75, 0) -> (35.56, 0)
  line L11 (30.48, 1.27) -> (31.75, 0)
  line L12 (35.56, 0) -> (36.83, 1.27)
create_component "CreateComponent2" sketch "Sketch1"
sketch "Sketch1"
  line L1 (2.032, -1.016) -> (-2.032, -1.016)
  line L2 (2.032, 1.016) -> (2.032, -1.016)
  line L3 (-2.032, 1.016) -> (2.032, 1.016)
  line L4 (-2.032, -1.016) -> (-2.032, 1.016)
create_component "CreateComponent3" sketch "Sketch1"
sketch "Sketch1"
  line L1 (2.6, -3.4) -> (-2.6, -3.4)
  line L2 (2.6, 3.4) -> (2.6, -3.4)
  line L3 (-2.6, 3.4) -> (2.6, 3.4)
  line L4 (-2.6, -3.4) -> (-2.6, 3.4)
create_component "CreateComponent4" sketch "Sketch1"
sketch "Sketch1"
  line L1 (2.032, -1.016) -> (-2.032, -1.016)
  line L2 (2.032, 1.016) -> (2.032, -1.016)
  line L3 (-2.032, 1.016) -> (2.032, 1.016)
  line L4 (-2.032, -1.016) -> (-2.032, 1.016)
create_component "CreateComponent5" sketch "Sketch1"
sketch "Sketch1"
  line L1 (4.19, -3.175) -> (-3.81, -3.175)
  line L2 (4.19, 3.175) -> (4.19, -3.175)
  line L3 (-3.81, 3.175) -> (4.19, 3.175)
  line L4 (-3.81, -3.175) -> (-3.81, 3.175)
create_component "CreateComponent6" sketch "Sketch1"
sketch "Sketch1"
  line L1 (1.689, -0.876) -> (-1.689, -0.876)
  line L2 (1.689, 0.876) -> (1.689, -0.876)
  line L3 (-1.689, 0.876) -> (1.689, 0.876)
  line L4 (-1.689, -0.876) -> (-1.689, 0.876)
create_component "CreateComponent7" sketch "Sketch1"
sketch "Sketch1"
  line L1 (4.19, -1.905) -> (-3.81, -1.905)
  line L2 (4.19, 1.905) -> (4.19, -1.905)
  line L3 (-3.81, 1.905) -> (4.19, 1.905)
  line L4 (-3.81, -1.905) -> (-3.81, 1.905)
create_component "CreateComponent8" sketch "Sketch1"
sketch "Sketch1"
  line L1 (1.422, -1.295) -> (-1.422, -1.295)
  line L2 (1.422, 1.295) -> (1.422, -1.295)
  line L3 (-1.422, 1.295) -> (1.422, 1.295)
  line L4 (-1.422, -1.295) -> (-1.422, 1.295)
canvas "Canvas3"
canvas "Canvas4"
create_component "CreateComponent9" sketch "Sketch1"
sketch "Sketch1"
  line L1 (2.032, -1.016) -> (-2.032, -1.016)
  line L2 (2.032, 1.016) -> (2.032, -1.016)
  line L3 (-2.032, 1.016) -> (2.032, 1.016)
  line L4 (-2.032, -1.016) -> (-2.032, 1.016)
create_component "CreateComponent10" sketch "Sketch1"
sketch "Sketch1"
  line L1 (2.032, -1.016) -> (-2.032, -1.016)
  line L2 (2.032, 1.016) -> (2.032, -1.016)
  line L3 (-2.032, 1.016) -> (2.032, 1.016)
  line L4 (-2.032, -1.016) -> (-2.032, 1.016)
as_built_joint "As-built2"
create_component "CreateComponent31"
create_component "CreateComponent32" sketch "Sketch46"
named bodies: "bottom", "top", "middle", "Race outer", "Race inner bottom", "Race inner top", "race inner", "race inner (1)", "Board", "C1206FAB", "SOIC14", "SOT23", "2X03SMD", "2X02SMD", "R1206FAB", "P-LCC-4", "PJ-002AH-SMT", "LED1206FAB", "1X06SMD", "EFOBM", "ELLCTV", "SOD123", "TO252", "BFC", "TQFP32-08", "SOIC8", "OP1206"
